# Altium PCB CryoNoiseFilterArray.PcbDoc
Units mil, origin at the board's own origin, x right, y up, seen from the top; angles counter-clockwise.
Board outline 9050 x 2175 mil, 2 copper layers (Top Layer, Bottom Layer); 0 components, 0 nets, 0 pads, 0 vias.
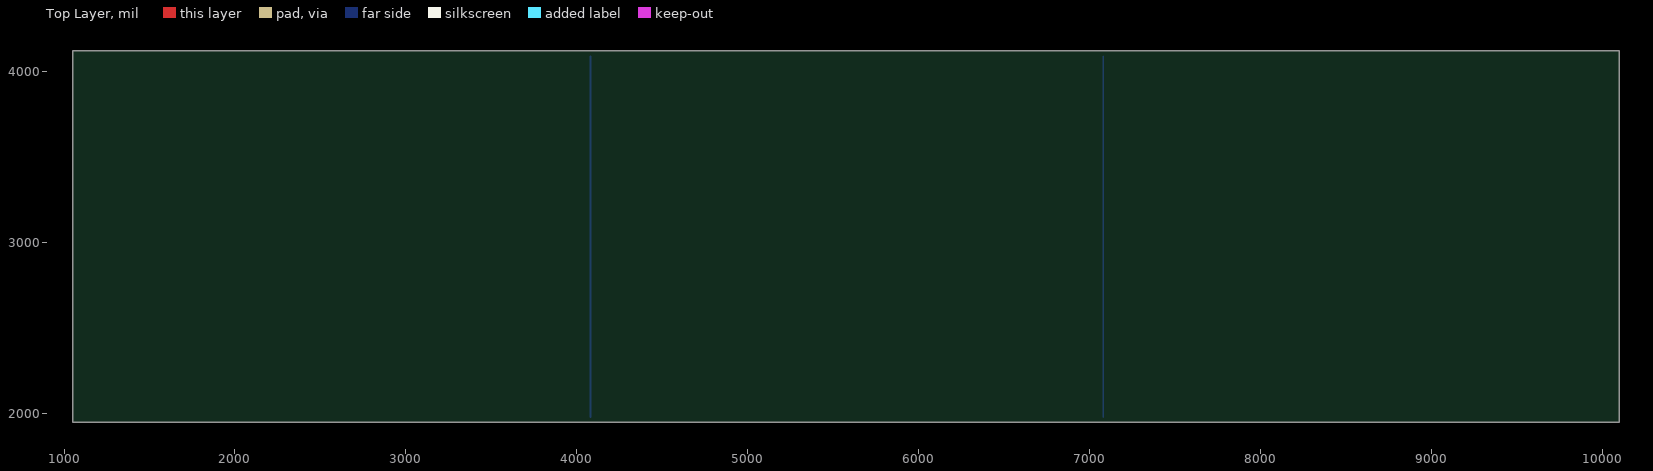
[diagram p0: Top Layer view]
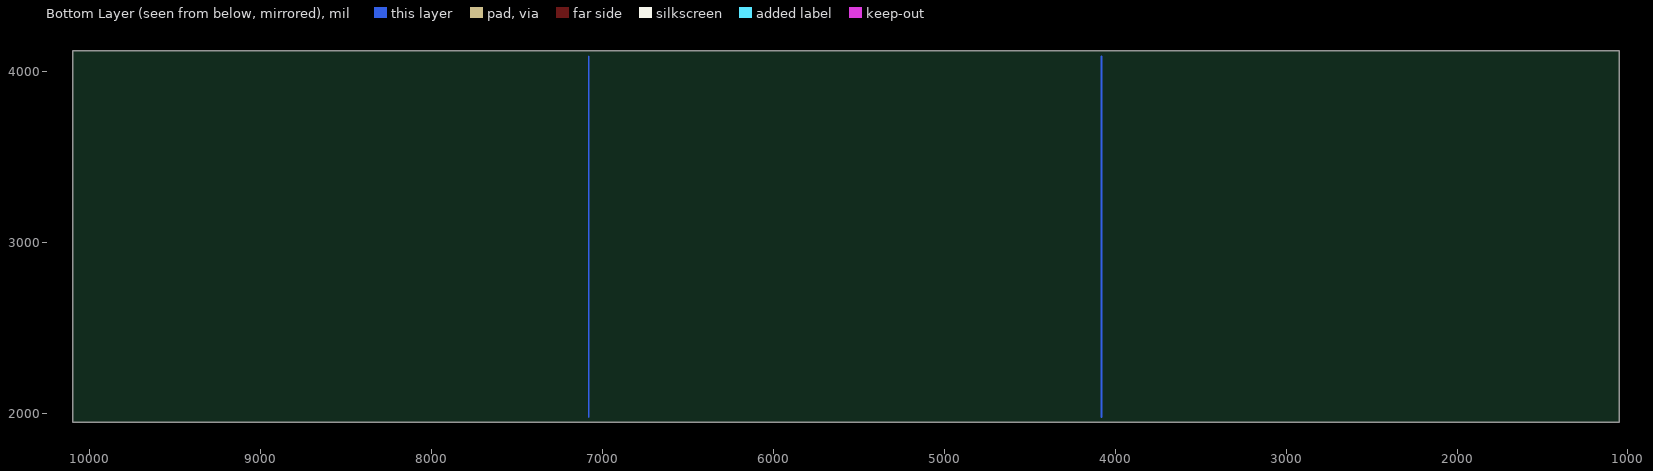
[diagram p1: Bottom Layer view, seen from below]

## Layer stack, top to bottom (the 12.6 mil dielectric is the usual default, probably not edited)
Top Layer: signal copper 1.4
Dielectric: dielectric 12.6, FR-4, Dk 4.8
Bottom Layer: signal copper 1.4

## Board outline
1050,1950 10100,1950 10100,4125 1050,4125

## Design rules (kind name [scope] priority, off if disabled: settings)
Clearance [All] p1: gap=10
PolygonConnect [All] p1: connectstyle=Relief reliefconductorwidth=10 reliefentries=4 polygonreliefangle="90 Angle"
RoutingVias [All] p1: holewidth=28 width=50 viastyle="Through Hole" minholewidth=28 minwidth=50 maxholewidth=28 maxwidth=50
SilkscreenOverComponentPads [All] p1: minsilkscreentomaskgap=10
SolderMaskExpansion [All] p1: expansion=4
Width [All] p1: maxlimit=10 minlimit=10 preferedwidth=10
27 further rules are at their usual default settings.

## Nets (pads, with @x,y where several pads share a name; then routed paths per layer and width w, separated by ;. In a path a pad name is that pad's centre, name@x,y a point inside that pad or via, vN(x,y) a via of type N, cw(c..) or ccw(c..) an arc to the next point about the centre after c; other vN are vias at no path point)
copper on no net: | length 4220
  Bottom Layer w10: 4080,1980 4080,4090 ; 7080,1980 7080,4090

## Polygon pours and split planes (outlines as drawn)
no net on Mechanical 1 "TopOverlay-No Net" (none): 1085,1980 1085,4090 10075,4090 10075,1980 1085,1980

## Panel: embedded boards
"CryoNoiseFilter.PcbDoc" at 1085,1980, 1 rows x 3 columns, spacing 2100 x 3000, rotation 0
